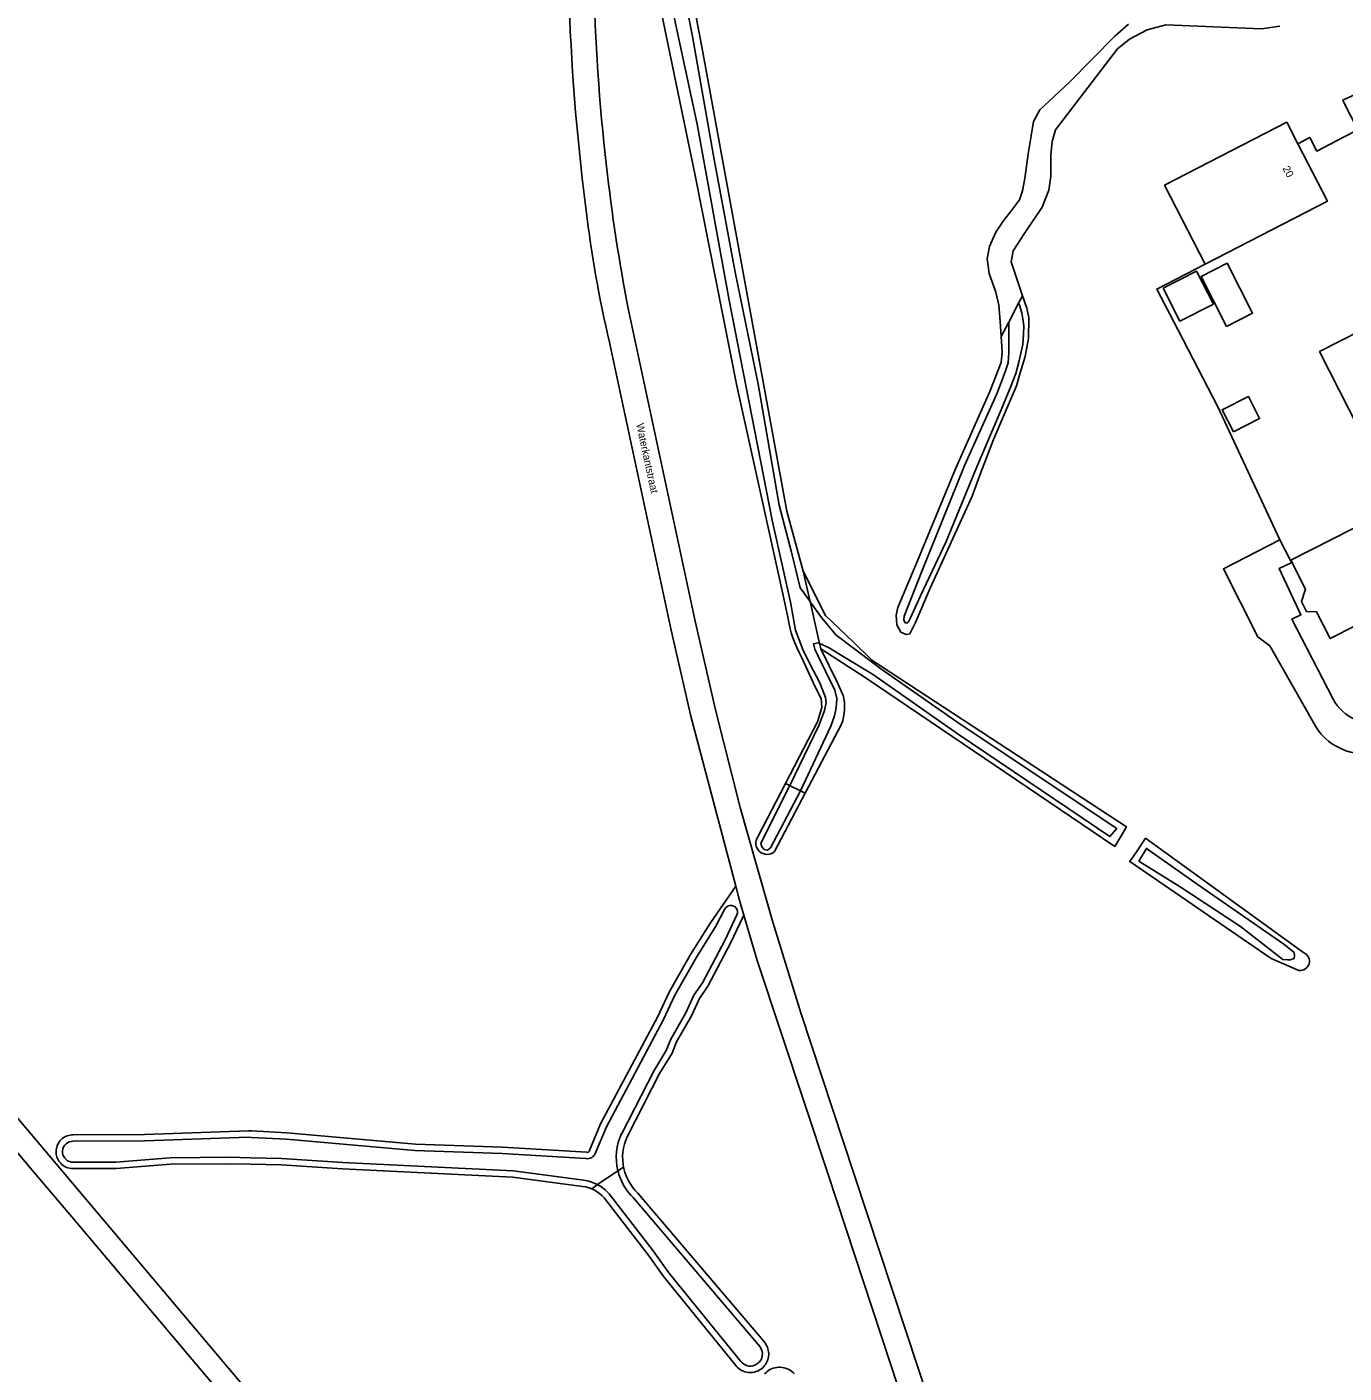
# Model space of a CAD drawing. Extents: x 158132 to 159658, y 385257 to 387209.
# Drawn here: x 158654.6 to 158829.4, y 386223.6 to 386402.3 of the extents above; entities that cross this region are included whole.
import ezdxf

# ---------------------------------------------------------------- set-up
doc = ezdxf.new("R2010")
doc.units = 0
for name, color, linetype in [('IMGEO_Gemengd_bos', 7, 'Continuous'), ('IMGEO_Oever', 7, 'Continuous'), ('IMGEO_Openbare_ruimte_label', 7, 'Continuous'), ('IMGEO_Pand', 7, 'Continuous'), ('IMGEO_Pand_nummerreeks', 7, 'Continuous'), ('IMGEO_Rijbaan_lokaal_gesloten', 7, 'Continuous'), ('IMGEO_Stuw', 7, 'Continuous'), ('IMGEO_Waterloop', 7, 'Continuous')]:
    doc.layers.add(name, color=color, linetype=linetype)

msp = doc.modelspace()

# ---------------------------------------------------------------- linework, layer by layer
at = {"layer": 'IMGEO_Gemengd_bos'}
for points in [[(158757.66, 386330.04), (158755.47, 386338), (158744.28, 386399.14), (158739.51, 386424.44)], [(158735.92, 386419.01), (158739.24, 386402.17), (158743.31, 386382.56), (158748.86, 386354.64), (158754.93, 386327.04), (158755.63, 386323.95)], [(158832.21, 386393.92), (158830.9, 386393.3), (158829.25, 386392.53), (158829.85, 386391.36), (158831.2, 386388.75), (158831.27, 386388.6), (158829.35, 386387.61), (158825.79, 386385.78), (158824.87, 386387.57), (158823.29, 386386.76)], [(158810.99, 386370.77), (158804.59, 386367.48), (158807.4, 386362.02), (158812.65, 386351.84), (158820.91, 386334.22)], [(158783.93, 386361.18), (158784.05, 386359.12), (158783.93, 386357.73), (158782.41, 386353.87), (158777.87, 386343.64), (158772.81, 386331.43), (158770.2, 386325.22), (158770, 386324.21), (158770.06, 386322.94), (158770.6, 386321.95), (158771.3, 386321.66), (158771.8, 386321.74), (158772.53, 386323.22), (158774.51, 386327.8), (158780.07, 386339.98), (158781.24, 386343.16), (158782.9, 386347.5), (158785.97, 386354.65), (158786.45, 386356.36), (158787.1, 386358.55), (158787.53, 386360.93), (158787.57, 386363.68), (158787.33, 386364.94), (158786.76, 386366.6)], [(158759.98, 386319.75), (158765.85, 386315.95), (158799, 386293.52), (158799.65, 386294.62), (158800.53, 386296.11), (158766.74, 386318.22), (158764.27, 386320.67), (158760.61, 386324.15), (158757.66, 386330.04)], [(158757.43, 386318.65), (158759.23, 386314.72), (158760.02, 386313.17), (158760.12, 386311.96), (158759.55, 386310.04), (158755.31, 386301.89)], [(158762.93, 386313.64), (158762.25, 386315.12), (158759.98, 386319.75)], [(158757.91, 386300.57), (158762.73, 386309.75)], [(158755.31, 386301.89), (158751.62, 386294.81)], [(158753.84, 386292.83), (158757.91, 386300.57)], [(158803.09, 386294.63), (158801.96, 386292.95), (158800.99, 386291.51), (158819.76, 386278.65), (158823.43, 386277.08)], [(158824.07, 386279.42), (158803.09, 386294.63)], [(158748.7, 386288.27), (158745.33, 386283.37), (158742.7, 386279.18), (158739.86, 386274.2), (158738.34, 386270.94), (158730.77, 386256.7), (158729.3, 386253.16), (158729.29, 386253.14), (158729.28, 386253.11), (158729.27, 386253.09), (158729.25, 386253.06), (158729.23, 386253.04), (158729.21, 386253.02), (158729.19, 386253), (158729.17, 386252.98), (158729.14, 386252.97), (158729.12, 386252.96), (158729.09, 386252.95), (158729.06, 386252.94), (158729.04, 386252.93), (158729.01, 386252.93), (158728.98, 386252.93), (158728.95, 386252.93), (158728.92, 386252.94), (158717.76, 386253.61), (158706.18, 386254.02), (158689.13, 386255.54), (158684.48, 386255.77), (158684.02, 386255.79), (158670.26, 386255.31), (158660.78, 386255.26), (158660.58, 386255.25), (158660.39, 386255.23), (158660.2, 386255.19), (158660.01, 386255.14), (158659.83, 386255.06), (158659.66, 386254.98), (158659.49, 386254.87), (158659.33, 386254.76), (158659.19, 386254.63), (158659.05, 386254.49), (158658.93, 386254.34), (158658.83, 386254.17), (158658.73, 386254), (158658.65, 386253.82), (158658.59, 386253.64), (158658.55, 386253.45), (158658.52, 386253.26), (158658.51, 386253.06), (158658.51, 386252.87), (158658.53, 386252.68), (158658.57, 386252.49), (158658.62, 386252.3), (158658.69, 386252.12), (158658.78, 386251.95), (158658.88, 386251.78), (158658.99, 386251.62), (158659.12, 386251.48), (158659.25, 386251.34), (158659.4, 386251.22), (158659.56, 386251.11), (158659.73, 386251.02), (158659.91, 386250.94), (158660.09, 386250.87), (158660.28, 386250.83), (158660.47, 386250.79), (158660.99, 386250.79), (158666.48, 386250.78), (158673.7, 386251.38), (158681.53, 386251.43), (158684.27, 386251.37), (158688.4, 386251.29), (158696.52, 386250.74), (158719.07, 386249.65), (158722.76, 386249.16), (158728.38, 386248.41), (158728.79, 386248.34), (158729.18, 386248.23), (158729.58, 386248.08)], [(158733.82, 386250.99), (158733.76, 386251.32), (158733.7, 386251.87), (158733.69, 386252.41), (158733.73, 386252.96), (158733.81, 386253.5), (158733.94, 386254.04), (158734.11, 386254.56), (158734.32, 386255.06), (158738.6, 386263.38), (158740.24, 386266.08), (158740.85, 386267.6), (158742.84, 386271.05), (158743.88, 386273.35), (158745.01, 386275), (158748.06, 386280.76), (158748.81, 386282.37), (158749.77, 386284.41)], [(158729.58, 386248.08), (158729.95, 386247.91), (158730.3, 386247.69), (158730.64, 386247.45), (158730.95, 386247.18), (158731.23, 386246.88), (158737.07, 386239.34), (158739.16, 386236.42), (158748.7, 386224.64), (158748.84, 386224.48), (158748.99, 386224.33), (158749.15, 386224.2), (158749.33, 386224.08), (158749.52, 386223.98), (158749.71, 386223.89), (158749.91, 386223.82), (158750.11, 386223.77), (158750.32, 386223.73), (158750.54, 386223.72), (158750.75, 386223.72), (158750.96, 386223.74), (158751.17, 386223.78), (158751.37, 386223.84), (158751.57, 386223.91), (158751.76, 386224), (158751.94, 386224.11), (158752.12, 386224.23), (158752.28, 386224.36), (158752.43, 386224.52), (158752.56, 386224.68), (158752.69, 386224.85), (158752.79, 386225.03), (158752.88, 386225.23), (158752.96, 386225.42), (158753.01, 386225.63), (158753.05, 386225.84), (158753.07, 386226.05), (158753.07, 386226.26), (158753.06, 386226.47), (158753.02, 386226.68), (158752.97, 386226.88), (158752.9, 386227.08), (158752.81, 386227.28), (158752.71, 386227.46), (158752.59, 386227.64), (158735.7, 386247.52), (158735.32, 386247.91), (158734.98, 386248.33), (158734.68, 386248.78), (158734.41, 386249.25), (158734.18, 386249.75), (158734, 386250.26), (158733.86, 386250.78), (158733.82, 386250.99)], [(158756.5, 386223.55), (158756.33, 386223.72), (158756.15, 386223.87), (158755.96, 386224), (158755.75, 386224.12), (158755.54, 386224.22), (158755.31, 386224.3), (158755.08, 386224.36), (158754.85, 386224.4), (158754.61, 386224.42), (158754.38, 386224.42), (158754.14, 386224.4), (158753.91, 386224.36), (158753.68, 386224.29), (158753.46, 386224.21), (158753.24, 386224.11), (158753.04, 386223.99), (158752.85, 386223.85), (158752.67, 386223.7), (158752.5, 386223.53)]]:
    msp.add_lwpolyline(points, dxfattribs=at)
for centre, radius, start, end in [((158770.02, 386325.89), 14.52, 187.7089, 209.9317), ((158756.71, 386312.01), 6.44, 339.4508, 14.6258), ((158752.86, 386293.97), 1.5, 146.1552, 310.4752), ((158823.61, 386278.29), 1.22, 261.507, 67.9497)]:
    msp.add_arc(centre, radius, start, end, dxfattribs=at)
at = {"layer": 'IMGEO_Oever'}
for points in [[(158758.57, 386325.99), (158757.66, 386330.04)], [(158759.98, 386319.75), (158759.82, 386320.45)], [(158755.86, 386301.61), (158755.31, 386301.89)], [(158757.91, 386300.57), (158757.3, 386300.88)], [(158733.82, 386250.99), (158733.05, 386250.5)], [(158730.36, 386248.65), (158729.58, 386248.08)]]:
    msp.add_lwpolyline(points, dxfattribs=at)
at = {"layer": 'IMGEO_Pand'}
for points in [[(158823.29, 386386.76), (158821.82, 386389.61), (158805.6, 386381.25), (158810.99, 386370.77)], [(158823.29, 386386.76), (158827.22, 386379.13), (158810.99, 386370.77)], [(158813.8, 386362.53), (158810.44, 386369.13), (158813.93, 386370.9), (158817.28, 386364.3), (158813.8, 386362.53)], [(158812.08, 386365.49), (158807.64, 386363.23), (158805.42, 386367.59), (158809.86, 386369.85), (158812.08, 386365.49)], [(158832.68, 386346.41), (158826.18, 386359.19), (158831.64, 386361.96)], [(158814.74, 386348.53), (158813.24, 386351.47), (158816.72, 386353.24), (158818.21, 386350.3), (158814.74, 386348.53)], [(158847.47, 386331.21), (158827.59, 386321.1), (158825.78, 386324.64), (158824.45, 386324.71), (158823.78, 386326.03), (158824.31, 386327.66), (158822.36, 386331.49), (158838.82, 386339.86)]]:
    msp.add_lwpolyline(points, dxfattribs=at)
at = {"layer": 'IMGEO_Rijbaan_lokaal_gesloten'}
for points in [[(158774.64, 386219.06), (158764.42, 386250), (158757.33, 386271.45), (158753.61, 386283.48), (158751.42, 386291.23), (158749.3, 386298.68), (158746.02, 386311.65), (158743.33, 386323.41), (158734.4, 386364.89)], [(158732.17, 386359.37), (158740.13, 386322.23), (158742.74, 386310.8), (158748.7, 386288.27)], [(158820.91, 386334.22), (158813.41, 386330.36), (158817.96, 386321.33), (158819.55, 386320.12), (158825.57, 386309.56)], [(158827.93, 386313.14), (158822.51, 386323.69), (158823.69, 386324.25), (158820.8, 386330.39), (158822.48, 386331.19), (158822.33, 386331.48), (158820.91, 386334.22)], [(158748.7, 386288.27), (158749.06, 386286.9), (158749.33, 386285.89), (158749.77, 386284.41)], [(158775.45, 386112.75), (158749.79, 386143.22), (158659.7, 386250), (158633.09, 386281.54), (158628.36, 386287.14)], [(158773.19, 386110.85), (158752.52, 386135.75), (158686.32, 386213.88), (158660.58, 386244.38), (158655.83, 386250), (158630.88, 386279.57), (158628.57, 386282.32), (158626.11, 386285.23)], [(158749.77, 386284.41), (158751.56, 386278.38), (158760.94, 386250), (158771.5, 386218.02)]]:
    msp.add_lwpolyline(points, dxfattribs=at)
for centre, radius, start, end in [((158993.77, 386414.07), 263.97, 181.1448, 186.5873), ((159028.95, 386416.44), 302.57, 182.1399, 187.5181), ((158997.01, 386414.38), 267.23, 186.5729, 190.6724), ((158891.98, 386397.6), 164.31, 187.2563, 193.4566), ((158833.58, 386316.16), 6.41, 208.1389, 246.3094), ((158832.26, 386313.6), 7.82, 211.1443, 290.2723)]:
    msp.add_arc(centre, radius, start, end, dxfattribs=at)
at = {"layer": 'IMGEO_Stuw'}
msp.add_lwpolyline([(158755.31, 386301.89), (158757.91, 386300.57)], dxfattribs=at)
at = {"layer": 'IMGEO_Waterloop'}
for points in [[(158755.86, 386301.61), (158759.76, 386309.67), (158760.48, 386311.56), (158760.7, 386312.64), (158760.61, 386313.27), (158759.84, 386315.24), (158758.56, 386317.68), (158757.58, 386319.65), (158756.63, 386322.21), (158755.98, 386325.92), (158753.51, 386336.81), (158747.76, 386366.21), (158743.56, 386389.35), (158736.69, 386421.47)], [(158740.93, 386411.36), (158742.95, 386400.97), (158745.84, 386384.66), (158748.64, 386369.72), (158751.69, 386354.85), (158754.48, 386338.82), (158756.11, 386332.57), (158757.24, 386327.82), (158758.56, 386326.01)], [(158800.81, 386402.64), (158799.01, 386401.01), (158793, 386394.95), (158789.04, 386391.27), (158788.23, 386389.73), (158787.92, 386387.79), (158787.49, 386385.42), (158787.07, 386382.16), (158786.77, 386380.49), (158786.33, 386379.3), (158785.31, 386377.92), (158784.19, 386376.5), (158783.21, 386375.01), (158782.37, 386373.12), (158782.05, 386371.49), (158782.33, 386369.52), (158783.21, 386367.08), (158783.63, 386365.34), (158783.8, 386363.18), (158783.93, 386361.18)], [(158786.76, 386366.6), (158785.23, 386371.11), (158785.5, 386372.55), (158786.99, 386374.81), (158789.34, 386378.34), (158790.24, 386380.6), (158790.51, 386382.45), (158790.51, 386385.25), (158790.7, 386387.05), (158791.15, 386388.59), (158799.37, 386399.34), (158800.95, 386400.65), (158803.3, 386401.87), (158805.78, 386402.55), (158818.48, 386402.01), (158820.92, 386402.37)], [(158784.92, 386363.08), (158784.93, 386362.98), (158784.95, 386361.71), (158784.95, 386360.14), (158784.93, 386359.02), (158784.83, 386357.71), (158784.48, 386356.61), (158783.9, 386355.1), (158783.34, 386353.57), (158779.11, 386344.16), (158773.43, 386330.15), (158771.04, 386324.06), (158771.02, 386323.58), (158771.15, 386323.25), (158771.41, 386323.15), (158771.62, 386323.34), (158771.84, 386323.77), (158772.12, 386324.35), (158773.23, 386326.78), (158776.63, 386333.99), (158780.71, 386343.87), (158783.9, 386351.44), (158785.17, 386354.46), (158785.85, 386356.27), (158786.27, 386357.77), (158786.59, 386359.14), (158786.78, 386360.13), (158786.89, 386361.48), (158786.91, 386362.62), (158786.81, 386363.54), (158786.64, 386364.31), (158786.35, 386365.32), (158786.24, 386365.61)], [(158784.92, 386363.08), (158786.24, 386365.61)], [(158786.24, 386365.61), (158786.76, 386366.6)], [(158783.93, 386361.18), (158784.92, 386363.08)], [(158758.56, 386326.01), (158758.57, 386325.99)], [(158758.56, 386326.01), (158759.81, 386320.45)], [(158759.82, 386320.45), (158761.02, 386319.93), (158763.16, 386318.61), (158766.84, 386316.37), (158778.23, 386308.43), (158798.36, 386294.83), (158799.25, 386295.89), (158778.63, 386309.67), (158767.97, 386317.08), (158765.03, 386319.3), (158761.96, 386321.58), (158760.09, 386323.89), (158758.57, 386325.99)], [(158759.81, 386320.45), (158759.65, 386320.52), (158759.01, 386320.42), (158759.18, 386319.68), (158759.62, 386318.76), (158760.63, 386316.77), (158761.85, 386314.25), (158762.11, 386313.17), (158762.04, 386311.91), (158761.81, 386310.87), (158761.32, 386309.5), (158757.3, 386300.88)], [(158759.82, 386320.45), (158759.81, 386320.45)], [(158757.3, 386300.88), (158753.32, 386293.34), (158752.89, 386293.01), (158752.47, 386293.11), (158752.17, 386293.48), (158752.03, 386293.96), (158755.86, 386301.61)], [(158809.92, 386288.52), (158803.2, 386293.25), (158802.19, 386291.57), (158807.68, 386288.16), (158815.66, 386282.9), (158821.28, 386278.52), (158821.9, 386278.46), (158822.28, 386278.47), (158822.8, 386278.65), (158822.85, 386279.06), (158822.78, 386279.44), (158821.41, 386280.57), (158809.92, 386288.52)], [(158747.22, 386285.16), (158746.07, 386282.95), (158743.43, 386278.75), (158740.62, 386273.81), (158739.1, 386270.56), (158731.54, 386256.33), (158730.1, 386252.86)], [(158733.56, 386255.44), (158737.86, 386263.79), (158739.47, 386266.46), (158740.08, 386267.97), (158742.08, 386271.44), (158743.14, 386273.77), (158744.29, 386275.44), (158747.3, 386281.14), (158748.84, 386284.43)], [(158728.82, 386252.1), (158717.72, 386252.76), (158706.13, 386253.17), (158689.07, 386254.69), (158684.43, 386254.92), (158684.02, 386254.94), (158670.28, 386254.46), (158660.77, 386254.41)], [(158660.53, 386251.64), (158666.45, 386251.63), (158673.66, 386252.22), (158681.54, 386252.28), (158684.29, 386252.22), (158688.44, 386252.14), (158696.57, 386251.59), (158719.15, 386250.49), (158722.87, 386250), (158728.49, 386249.26)], [(158730.36, 386248.65), (158733.05, 386250.5)], [(158733.05, 386250.5), (158733.12, 386250.25), (158733.19, 386250)], [(158749.36, 386225.17), (158739.83, 386236.94), (158737.75, 386239.85), (158731.89, 386247.42)], [(158735.08, 386246.94), (158751.93, 386227.11)]]:
    msp.add_lwpolyline(points, dxfattribs=at)
for centre, radius, start, end in [((158748.04, 386284.81), 0.887, 335.1598, 156.5939), ((158660.75, 386253.02), 1.39, 88.8398, 261.0137), ((158740.27, 386252.25), 7.43, 154.6234, 193.6174), ((158728.99, 386253.26), 1.17, 261.6924, 340.4332), ((158727.74, 386243.79), 5.52, 61.6778, 82.136), ((158740.19, 386252.2), 7.33, 197.4602, 225.8446), ((158727.74, 386243.81), 5.5, 41.0587, 61.6126), ((158750.62, 386226.18), 1.61, 218.652, 35.6147)]:
    msp.add_arc(centre, radius, start, end, dxfattribs=at)

# ---------------------------------------------------------------- texts
at = {"layer": 'IMGEO_Openbare_ruimte_label'}
msp.add_text('Waterkantstraat', height=1, rotation=282.1308, dxfattribs=at).set_placement((158735.48, 386349.55))
at = {"layer": 'IMGEO_Pand_nummerreeks'}
msp.add_text('20', height=1, rotation=297.6221, dxfattribs=at).set_placement((158821.22, 386383.5))

doc.saveas('drawing.dxf')
